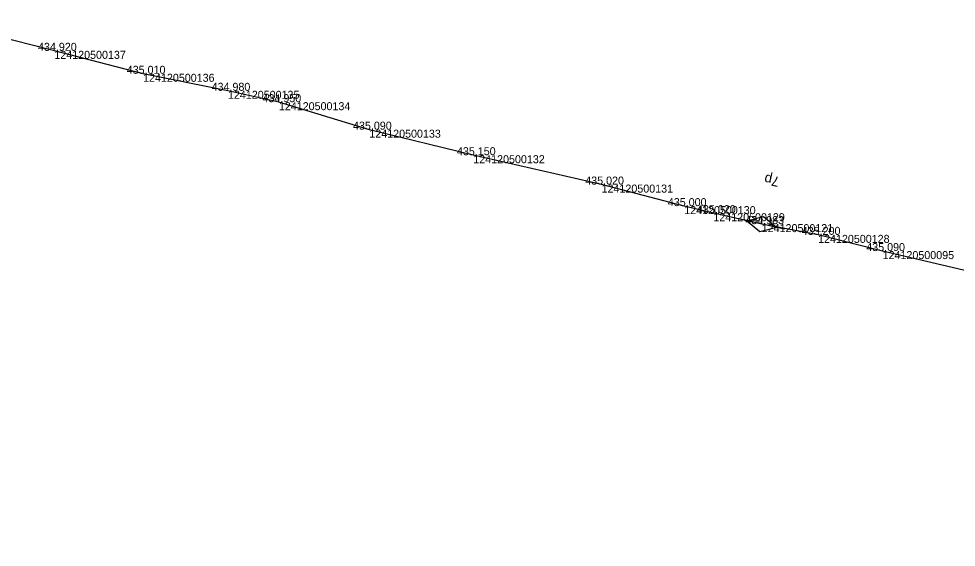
# Model space of a CAD drawing. Extents: x -637342 to -635997, y -1153616 to -1153154.
# Drawn here: x -636484.6 to -636344.1, y -1153521.6 to -1153442.4 of the extents above; entities that cross this region are included whole.
import ezdxf

# ---------------------------------------------------------------- set-up
doc = ezdxf.new("R2010")
doc.units = 0
for name, color, linetype in [('Vrstva 28', 7, 'Continuous'), ('Vrstva 60', 7, 'Continuous'), ('Vrstva 61', 7, 'Continuous')]:
    doc.layers.add(name, color=color, linetype=linetype)

msp = doc.modelspace()

# ---------------------------------------------------------------- linework, layer by layer
at = {"layer": 'Vrstva 28'}
for p, q in [((-636369.84, -1153473.95), (-636376.65, -1153472.42)), ((-636375.52, -1153472.68), (-636372.99, -1153472.05)), ((-636373.5, -1153474.32), (-636375.52, -1153472.68)), ((-636372.99, -1153472.05), (-636370.97, -1153473.69)), ((-636370.97, -1153473.69), (-636373.5, -1153474.32))]:
    msp.add_line(p, q, dxfattribs=at)
for points in [[(-636355.12, -1153477.23), (-636364.79, -1153474.8), (-636373.24, -1153473.19), (-636380.49, -1153471.55), (-636384.86, -1153470.49), (-636397.24, -1153467.26), (-636416.47, -1153462.86), (-636432.05, -1153459.03), (-636445.61, -1153454.91), (-636453.24, -1153453.2), (-636465.96, -1153450.65), (-636479.26, -1153447.21), (-636498.16, -1153442.4)], [(-636209.15, -1153521.63), (-636217.81, -1153519.84), (-636221.73, -1153518.53), (-636222.97, -1153518.15), (-636223.35, -1153518.3), (-636226.18, -1153517.17), (-636235.77, -1153514.24), (-636237.04, -1153515.3), (-636238.84, -1153516.2), (-636238.99, -1153516.01), (-636248.63, -1153511.83), (-636253.91, -1153509.89), (-636265.9, -1153505.24), (-636278.13, -1153501.04), (-636291.59, -1153495.18), (-636303.97, -1153491.53), (-636321.14, -1153486.88), (-636341.28, -1153480.5), (-636355.12, -1153477.23)]]:
    msp.add_lwpolyline(points, dxfattribs=at)
at = {"layer": 'Vrstva 60'}
for p, q in [((-636479.26, -1153447.21), (-636479.26, -1153447.21)), ((-636465.96, -1153450.65), (-636465.96, -1153450.65)), ((-636453.24, -1153453.2), (-636453.24, -1153453.2)), ((-636445.61, -1153454.91), (-636445.61, -1153454.91)), ((-636432.05, -1153459.03), (-636432.05, -1153459.03)), ((-636416.47, -1153462.86), (-636416.47, -1153462.86)), ((-636397.24, -1153467.26), (-636397.24, -1153467.26)), ((-636384.86, -1153470.49), (-636384.86, -1153470.49)), ((-636380.49, -1153471.55), (-636380.49, -1153471.55)), ((-636373.24, -1153473.19), (-636373.24, -1153473.19)), ((-636364.79, -1153474.8), (-636364.79, -1153474.8)), ((-636355.12, -1153477.23), (-636355.12, -1153477.23))]:
    msp.add_line(p, q, dxfattribs=at)

# ---------------------------------------------------------------- texts
at = {"layer": 'Vrstva 28'}
msp.add_text('7p', height=1.5, rotation=167.4193, dxfattribs=at).set_placement((-636370.49, -1153466.17))
at = {"layer": 'Vrstva 60'}
for s, p in [('124120500137', (-636479.26, -1153448.41)), ('124120500136', (-636465.96, -1153451.85)), ('124120500135', (-636453.24, -1153454.4)), ('124120500134', (-636445.61, -1153456.11)), ('124120500133', (-636432.05, -1153460.23)), ('124120500132', (-636416.47, -1153464.06)), ('124120500131', (-636397.24, -1153468.46)), ('124120500130', (-636384.86, -1153471.69)), ('124120500129', (-636380.49, -1153472.75)), ('124120500121', (-636373.24, -1153474.39)), ('124120500128', (-636364.79, -1153476)), ('124120500095', (-636355.12, -1153478.43))]:
    msp.add_text(s, height=1.2, dxfattribs=at).set_placement(p)
at = {"layer": 'Vrstva 61'}
for s, p in [('434.920', (-636481.71, -1153447.21)), ('435.010', (-636468.41, -1153450.65)), ('434.980', (-636455.69, -1153453.2)), ('434.950', (-636448.06, -1153454.91)), ('435.090', (-636434.5, -1153459.03)), ('435.150', (-636418.92, -1153462.86)), ('435.020', (-636399.69, -1153467.26)), ('435.000', (-636387.31, -1153470.49)), ('435.020', (-636382.94, -1153471.55)), ('434.983', (-636375.7, -1153473.19)), ('435.200', (-636367.24, -1153474.8)), ('435.090', (-636357.57, -1153477.23))]:
    msp.add_text(s, height=1.2, dxfattribs=at).set_placement(p)

doc.saveas('drawing.dxf')
